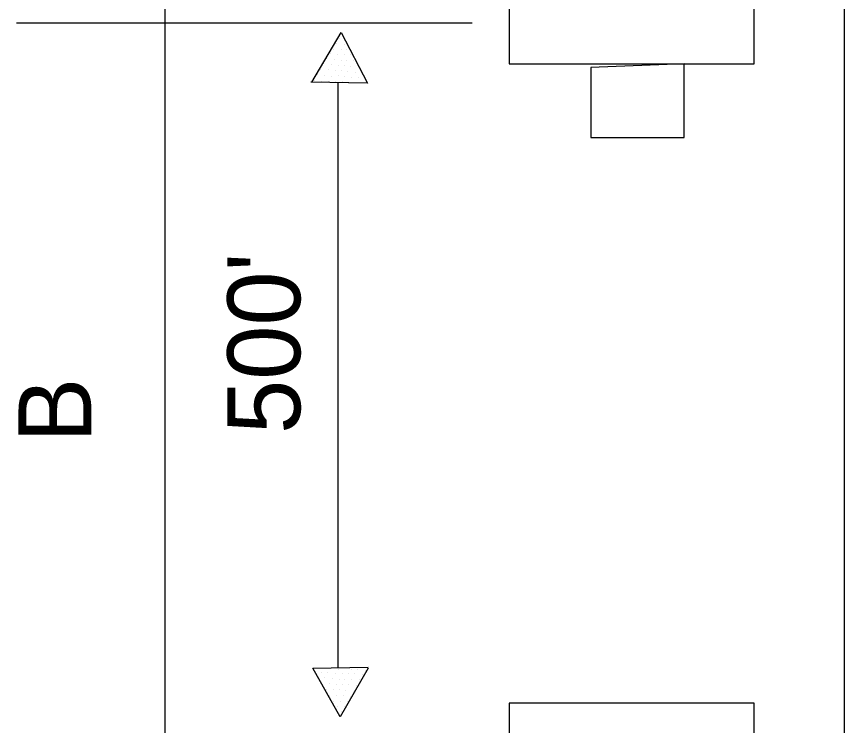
# Model space of a CAD drawing. Extents: x 610.92 to 617.75, y 610.91 to 620.34.
# Drawn here: x 615.127 to 615.809, y 618.599 to 619.182 of the extents above; entities that cross this region are included whole.
import ezdxf

# ---------------------------------------------------------------- set-up
doc = ezdxf.new("R2010")
doc.units = 0
for name, color, linetype in [('DETL-DIMS', 7, 'Continuous'), ('DETL-LINE', 7, 'Continuous'), ('DETL-NOTE', 7, 'Continuous'), ('USER-BORD', 7, 'Continuous')]:
    doc.layers.add(name, color=color, linetype=linetype)

# ---------------------------------------------------------------- blocks, each defined once
blk = doc.blocks.new('SIGN15')
at = {"layer": 'USER-BORD'}
for points in [[(-0.0013, 0.0018), (0.0011, 0.0019), (0.0011, 0.0037), (-0.0013, 0.0037)], [(-0.0031, 0.0018), (-0.0031, 0), (0.0032, 0), (0.0032, 0.0018)]]:
    blk.add_lwpolyline(points, close=True, dxfattribs=at)

msp = doc.modelspace()

# ---------------------------------------------------------------- linework, layer by layer
at = {"layer": 'DETL-DIMS'}
for p, q in [((615.24936, 618.082), (615.24936, 619.7948)), ((615.12696, 619.1772), (615.50216, 619.1772)), ((615.37016, 619.1284), (615.39416, 619.1692)), ((615.37016, 619.1284), (615.39416, 619.1692)), ((615.37016, 619.1284), (615.39416, 619.1692)), ((615.37016, 619.1284), (615.39416, 619.1692)), ((615.39416, 619.1692), (615.41576, 619.1276)), ((615.39416, 619.1692), (615.41576, 619.1276)), ((615.39416, 619.1692), (615.41576, 619.1276)), ((615.39416, 619.1692), (615.41576, 619.1276)), ((615.39016, 619.1604), (615.39016, 619.1604)), ((615.39016, 619.1604), (615.39016, 619.1604)), ((615.39016, 619.1604), (615.39016, 619.1604)), ((615.39016, 619.1604), (615.39016, 619.1604)), ((615.39256, 619.1644), (615.39256, 619.1644)), ((615.39256, 619.1644), (615.39256, 619.1644)), ((615.39256, 619.1644), (615.39256, 619.1644)), ((615.39256, 619.1644), (615.39256, 619.1644)), ((615.39656, 619.1596), (615.39656, 619.1596)), ((615.39656, 619.1596), (615.39656, 619.1596)), ((615.39656, 619.1596), (615.39656, 619.1596)), ((615.39656, 619.1596), (615.39656, 619.1596)), ((615.38776, 619.1556), (615.38776, 619.1556)), ((615.38776, 619.1556), (615.38776, 619.1556)), ((615.38776, 619.1556), (615.38776, 619.1556)), ((615.38776, 619.1556), (615.38776, 619.1556)), ((615.39416, 619.1556), (615.39416, 619.1556)), ((615.39416, 619.1556), (615.39416, 619.1556)), ((615.39416, 619.1556), (615.39416, 619.1556)), ((615.39416, 619.1556), (615.39416, 619.1556)), ((615.39896, 619.1556), (615.39896, 619.1556)), ((615.39896, 619.1556), (615.39896, 619.1556)), ((615.39896, 619.1556), (615.39896, 619.1556)), ((615.39896, 619.1556), (615.39896, 619.1556)), ((615.38216, 619.1476), (615.38216, 619.1476)), ((615.38216, 619.1476), (615.38216, 619.1476)), ((615.38216, 619.1476), (615.38216, 619.1476)), ((615.38216, 619.1476), (615.38216, 619.1476)), ((615.38536, 619.1516), (615.38536, 619.1516)), ((615.38536, 619.1516), (615.38536, 619.1516)), ((615.38536, 619.1516), (615.38536, 619.1516)), ((615.38536, 619.1516), (615.38536, 619.1516)), ((615.38856, 619.1468), (615.38856, 619.1468)), ((615.38856, 619.1468), (615.38856, 619.1468)), ((615.38856, 619.1468), (615.38856, 619.1468)), ((615.38856, 619.1468), (615.38856, 619.1468)), ((615.39096, 619.1508), (615.39096, 619.1508)), ((615.39096, 619.1508), (615.39096, 619.1508)), ((615.39096, 619.1508), (615.39096, 619.1508)), ((615.39096, 619.1508), (615.39096, 619.1508)), ((615.39416, 619.146), (615.39416, 619.146)), ((615.39416, 619.146), (615.39416, 619.146)), ((615.39416, 619.146), (615.39416, 619.146)), ((615.39416, 619.146), (615.39416, 619.146)), ((615.39656, 619.1508), (615.39656, 619.1508)), ((615.39656, 619.1508), (615.39656, 619.1508)), ((615.39656, 619.1508), (615.39656, 619.1508)), ((615.39656, 619.1508), (615.39656, 619.1508)), ((615.39896, 619.146), (615.39896, 619.146)), ((615.39896, 619.146), (615.39896, 619.146)), ((615.39896, 619.146), (615.39896, 619.146)), ((615.39896, 619.146), (615.39896, 619.146)), ((615.40216, 619.1508), (615.40216, 619.1508)), ((615.40216, 619.1508), (615.40216, 619.1508)), ((615.40216, 619.1508), (615.40216, 619.1508)), ((615.40216, 619.1508), (615.40216, 619.1508)), ((615.40456, 619.146), (615.40456, 619.146)), ((615.40456, 619.146), (615.40456, 619.146)), ((615.40456, 619.146), (615.40456, 619.146)), ((615.40456, 619.146), (615.40456, 619.146)), ((615.37736, 619.1388), (615.37736, 619.1388)), ((615.37736, 619.1388), (615.37736, 619.1388)), ((615.37736, 619.1388), (615.37736, 619.1388)), ((615.37736, 619.1388), (615.37736, 619.1388)), ((615.37976, 619.1436), (615.37976, 619.1436)), ((615.37976, 619.1436), (615.37976, 619.1436)), ((615.37976, 619.1436), (615.37976, 619.1436)), ((615.37976, 619.1436), (615.37976, 619.1436)), ((615.38376, 619.1388), (615.38376, 619.1388)), ((615.38376, 619.1388), (615.38376, 619.1388)), ((615.38376, 619.1388), (615.38376, 619.1388)), ((615.38376, 619.1388), (615.38376, 619.1388)), ((615.38616, 619.1428), (615.38616, 619.1428)), ((615.38616, 619.1428), (615.38616, 619.1428)), ((615.38616, 619.1428), (615.38616, 619.1428)), ((615.38616, 619.1428), (615.38616, 619.1428)), ((615.39176, 619.142), (615.39176, 619.142)), ((615.39176, 619.142), (615.39176, 619.142)), ((615.39176, 619.142), (615.39176, 619.142)), ((615.39176, 619.142), (615.39176, 619.142)), ((615.39656, 619.142), (615.39656, 619.142)), ((615.39656, 619.142), (615.39656, 619.142)), ((615.39656, 619.142), (615.39656, 619.142)), ((615.39656, 619.142), (615.39656, 619.142)), ((615.40216, 619.1412), (615.40216, 619.1412)), ((615.40216, 619.1412), (615.40216, 619.1412)), ((615.40216, 619.1412), (615.40216, 619.1412)), ((615.40216, 619.1412), (615.40216, 619.1412)), ((615.40856, 619.1404), (615.40856, 619.1404)), ((615.40856, 619.1404), (615.40856, 619.1404)), ((615.40856, 619.1404), (615.40856, 619.1404)), ((615.40856, 619.1404), (615.40856, 619.1404)), ((615.37496, 619.1348), (615.37496, 619.1348)), ((615.37496, 619.1348), (615.37496, 619.1348)), ((615.37496, 619.1348), (615.37496, 619.1348)), ((615.37496, 619.1348), (615.37496, 619.1348)), ((615.38056, 619.134), (615.38056, 619.134)), ((615.38056, 619.134), (615.38056, 619.134)), ((615.38056, 619.134), (615.38056, 619.134)), ((615.38056, 619.134), (615.38056, 619.134)), ((615.38616, 619.1332), (615.38616, 619.1332)), ((615.38616, 619.1332), (615.38616, 619.1332)), ((615.38616, 619.1332), (615.38616, 619.1332)), ((615.38616, 619.1332), (615.38616, 619.1332)), ((615.38936, 619.138), (615.38936, 619.138)), ((615.38936, 619.138), (615.38936, 619.138)), ((615.38936, 619.138), (615.38936, 619.138)), ((615.38936, 619.138), (615.38936, 619.138)), ((615.39176, 619.134), (615.39176, 619.134)), ((615.39176, 619.134), (615.39176, 619.134)), ((615.39176, 619.134), (615.39176, 619.134)), ((615.39176, 619.134), (615.39176, 619.134)), ((615.39416, 619.138), (615.39416, 619.138)), ((615.39416, 619.138), (615.39416, 619.138)), ((615.39416, 619.138), (615.39416, 619.138)), ((615.39416, 619.138), (615.39416, 619.138)), ((615.39736, 619.1332), (615.39736, 619.1332)), ((615.39736, 619.1332), (615.39736, 619.1332)), ((615.39736, 619.1332), (615.39736, 619.1332)), ((615.39736, 619.1332), (615.39736, 619.1332)), ((615.39976, 619.1372), (615.39976, 619.1372)), ((615.39976, 619.1372), (615.39976, 619.1372)), ((615.39976, 619.1372), (615.39976, 619.1372)), ((615.39976, 619.1372), (615.39976, 619.1372)), ((615.40296, 619.1324), (615.40296, 619.1324)), ((615.40296, 619.1324), (615.40296, 619.1324)), ((615.40296, 619.1324), (615.40296, 619.1324)), ((615.40296, 619.1324), (615.40296, 619.1324)), ((615.40616, 619.1364), (615.40616, 619.1364)), ((615.40616, 619.1364), (615.40616, 619.1364)), ((615.40616, 619.1364), (615.40616, 619.1364)), ((615.40616, 619.1364), (615.40616, 619.1364)), ((615.40856, 619.1324), (615.40856, 619.1324)), ((615.40856, 619.1324), (615.40856, 619.1324)), ((615.40856, 619.1324), (615.40856, 619.1324)), ((615.40856, 619.1324), (615.40856, 619.1324)), ((615.36936, 619.1284), (615.36936, 619.1284)), ((615.41576, 619.1276), (615.36936, 619.1284)), ((615.41576, 619.1276), (615.36936, 619.1284)), ((615.36936, 619.1284), (615.36936, 619.1284)), ((615.36936, 619.1284), (615.36936, 619.1284)), ((615.41576, 619.1276), (615.36936, 619.1284)), ((615.41576, 619.1276), (615.36936, 619.1284)), ((615.36936, 619.1284), (615.36936, 619.1284)), ((615.37256, 619.13), (615.37256, 619.13)), ((615.37256, 619.13), (615.37256, 619.13)), ((615.37256, 619.13), (615.37256, 619.13)), ((615.37256, 619.13), (615.37256, 619.13)), ((615.37816, 619.1292), (615.37816, 619.1292)), ((615.37816, 619.1292), (615.37816, 619.1292)), ((615.37816, 619.1292), (615.37816, 619.1292)), ((615.37816, 619.1292), (615.37816, 619.1292)), ((615.38376, 619.1292), (615.38376, 619.1292)), ((615.38376, 619.1292), (615.38376, 619.1292)), ((615.38376, 619.1292), (615.38376, 619.1292)), ((615.38376, 619.1292), (615.38376, 619.1292)), ((615.38936, 619.1292), (615.38936, 619.1292)), ((615.38936, 619.1292), (615.38936, 619.1292)), ((615.38936, 619.1292), (615.38936, 619.1292)), ((615.38936, 619.1292), (615.38936, 619.1292)), ((615.39176, 618.6468), (615.39176, 619.1284)), ((615.39496, 619.1292), (615.39496, 619.1292)), ((615.39496, 619.1292), (615.39496, 619.1292)), ((615.39496, 619.1292), (615.39496, 619.1292)), ((615.39496, 619.1292), (615.39496, 619.1292)), ((615.40056, 619.1284), (615.40056, 619.1284)), ((615.40056, 619.1284), (615.40056, 619.1284)), ((615.40056, 619.1284), (615.40056, 619.1284)), ((615.40056, 619.1284), (615.40056, 619.1284)), ((615.39176, 618.6692), (615.39176, 619.0932)), ((615.39176, 618.6692), (615.39176, 619.0932)), ((615.39176, 618.6692), (615.39176, 619.0932)), ((615.37096, 618.646), (615.41656, 618.6468)), ((615.37096, 618.646), (615.41656, 618.6468)), ((615.37096, 618.646), (615.41656, 618.6468)), ((615.37096, 618.646), (615.41656, 618.6468)), ((615.39336, 618.606), (615.37096, 618.646)), ((615.39336, 618.606), (615.37096, 618.646)), ((615.39336, 618.606), (615.37096, 618.646)), ((615.39336, 618.606), (615.37096, 618.646)), ((615.37816, 618.642), (615.37816, 618.642)), ((615.37816, 618.642), (615.37816, 618.642)), ((615.37816, 618.642), (615.37816, 618.642)), ((615.37816, 618.642), (615.37816, 618.642)), ((615.38296, 618.642), (615.38296, 618.642)), ((615.38296, 618.642), (615.38296, 618.642)), ((615.38296, 618.642), (615.38296, 618.642)), ((615.38296, 618.642), (615.38296, 618.642)), ((615.38536, 618.646), (615.38536, 618.646)), ((615.38536, 618.646), (615.38536, 618.646)), ((615.38536, 618.646), (615.38536, 618.646)), ((615.38536, 618.646), (615.38536, 618.646)), ((615.38936, 618.6412), (615.38936, 618.6412)), ((615.38936, 618.6412), (615.38936, 618.6412)), ((615.38936, 618.6412), (615.38936, 618.6412)), ((615.38936, 618.6412), (615.38936, 618.6412)), ((615.39176, 618.6452), (615.39176, 618.6452)), ((615.39176, 618.6452), (615.39176, 618.6452)), ((615.39176, 618.6452), (615.39176, 618.6452)), ((615.39176, 618.6452), (615.39176, 618.6452)), ((615.41656, 618.646), (615.39336, 618.606)), ((615.41656, 618.646), (615.39336, 618.606)), ((615.41656, 618.646), (615.39336, 618.606)), ((615.41656, 618.646), (615.39336, 618.606)), ((615.39496, 618.6412), (615.39496, 618.6412)), ((615.39496, 618.6412), (615.39496, 618.6412)), ((615.39496, 618.6412), (615.39496, 618.6412)), ((615.39496, 618.6412), (615.39496, 618.6412)), ((615.39736, 618.646), (615.39736, 618.646)), ((615.39736, 618.646), (615.39736, 618.646)), ((615.39736, 618.646), (615.39736, 618.646)), ((615.39736, 618.646), (615.39736, 618.646)), ((615.40056, 618.6412), (615.40056, 618.6412)), ((615.40056, 618.6412), (615.40056, 618.6412)), ((615.40056, 618.6412), (615.40056, 618.6412)), ((615.40056, 618.6412), (615.40056, 618.6412)), ((615.40296, 618.6452), (615.40296, 618.6452)), ((615.40296, 618.6452), (615.40296, 618.6452)), ((615.40296, 618.6452), (615.40296, 618.6452)), ((615.40296, 618.6452), (615.40296, 618.6452)), ((615.40536, 618.6412), (615.40536, 618.6412)), ((615.40536, 618.6412), (615.40536, 618.6412)), ((615.40536, 618.6412), (615.40536, 618.6412)), ((615.40536, 618.6412), (615.40536, 618.6412)), ((615.40776, 618.6452), (615.40776, 618.6452)), ((615.40776, 618.6452), (615.40776, 618.6452)), ((615.40776, 618.6452), (615.40776, 618.6452)), ((615.40776, 618.6452), (615.40776, 618.6452)), ((615.41416, 618.6444), (615.41416, 618.6444)), ((615.41416, 618.6444), (615.41416, 618.6444)), ((615.41416, 618.6444), (615.41416, 618.6444)), ((615.41416, 618.6444), (615.41416, 618.6444)), ((615.41656, 618.6468), (615.41656, 618.6468)), ((615.41656, 618.6468), (615.41656, 618.6468)), ((615.41656, 618.6468), (615.41656, 618.6468)), ((615.41656, 618.6468), (615.41656, 618.6468)), ((615.38056, 618.638), (615.38056, 618.638)), ((615.38056, 618.638), (615.38056, 618.638)), ((615.38056, 618.638), (615.38056, 618.638)), ((615.38056, 618.638), (615.38056, 618.638)), ((615.38696, 618.6372), (615.38696, 618.6372)), ((615.38696, 618.6372), (615.38696, 618.6372)), ((615.38696, 618.6372), (615.38696, 618.6372)), ((615.38696, 618.6372), (615.38696, 618.6372)), ((615.39256, 618.6364), (615.39256, 618.6364)), ((615.39256, 618.6364), (615.39256, 618.6364)), ((615.39256, 618.6364), (615.39256, 618.6364)), ((615.39256, 618.6364), (615.39256, 618.6364)), ((615.39736, 618.6364), (615.39736, 618.6364)), ((615.39736, 618.6364), (615.39736, 618.6364)), ((615.39736, 618.6364), (615.39736, 618.6364)), ((615.39736, 618.6364), (615.39736, 618.6364)), ((615.40296, 618.6364), (615.40296, 618.6364)), ((615.40296, 618.6364), (615.40296, 618.6364)), ((615.40296, 618.6364), (615.40296, 618.6364)), ((615.40296, 618.6364), (615.40296, 618.6364)), ((615.40936, 618.6364), (615.40936, 618.6364)), ((615.40936, 618.6364), (615.40936, 618.6364)), ((615.40936, 618.6364), (615.40936, 618.6364)), ((615.40936, 618.6364), (615.40936, 618.6364)), ((615.41176, 618.6404), (615.41176, 618.6404)), ((615.41176, 618.6404), (615.41176, 618.6404)), ((615.41176, 618.6404), (615.41176, 618.6404)), ((615.41176, 618.6404), (615.41176, 618.6404)), ((615.37816, 618.6332), (615.37816, 618.6332)), ((615.37816, 618.6332), (615.37816, 618.6332)), ((615.37816, 618.6332), (615.37816, 618.6332)), ((615.37816, 618.6332), (615.37816, 618.6332)), ((615.38216, 618.6284), (615.38216, 618.6284)), ((615.38216, 618.6284), (615.38216, 618.6284)), ((615.38216, 618.6284), (615.38216, 618.6284)), ((615.38216, 618.6284), (615.38216, 618.6284)), ((615.38456, 618.6332), (615.38456, 618.6332)), ((615.38456, 618.6332), (615.38456, 618.6332)), ((615.38456, 618.6332), (615.38456, 618.6332)), ((615.38456, 618.6332), (615.38456, 618.6332)), ((615.38776, 618.6284), (615.38776, 618.6284)), ((615.38776, 618.6284), (615.38776, 618.6284)), ((615.38776, 618.6284), (615.38776, 618.6284)), ((615.38776, 618.6284), (615.38776, 618.6284)), ((615.39016, 618.6324), (615.39016, 618.6324)), ((615.39016, 618.6324), (615.39016, 618.6324)), ((615.39016, 618.6324), (615.39016, 618.6324)), ((615.39016, 618.6324), (615.39016, 618.6324)), ((615.39256, 618.6284), (615.39256, 618.6284)), ((615.39256, 618.6284), (615.39256, 618.6284)), ((615.39256, 618.6284), (615.39256, 618.6284)), ((615.39256, 618.6284), (615.39256, 618.6284)), ((615.39496, 618.6324), (615.39496, 618.6324)), ((615.39496, 618.6324), (615.39496, 618.6324)), ((615.39496, 618.6324), (615.39496, 618.6324)), ((615.39496, 618.6324), (615.39496, 618.6324)), ((615.39816, 618.6276), (615.39816, 618.6276)), ((615.39816, 618.6276), (615.39816, 618.6276)), ((615.39816, 618.6276), (615.39816, 618.6276)), ((615.39816, 618.6276), (615.39816, 618.6276)), ((615.40056, 618.6324), (615.40056, 618.6324)), ((615.40056, 618.6324), (615.40056, 618.6324)), ((615.40056, 618.6324), (615.40056, 618.6324)), ((615.40056, 618.6324), (615.40056, 618.6324)), ((615.40696, 618.6316), (615.40696, 618.6316)), ((615.40696, 618.6316), (615.40696, 618.6316)), ((615.40696, 618.6316), (615.40696, 618.6316)), ((615.40696, 618.6316), (615.40696, 618.6316)), ((615.38456, 618.6236), (615.38456, 618.6236)), ((615.38456, 618.6236), (615.38456, 618.6236)), ((615.38456, 618.6236), (615.38456, 618.6236)), ((615.38456, 618.6236), (615.38456, 618.6236)), ((615.39016, 618.6236), (615.39016, 618.6236)), ((615.39016, 618.6236), (615.39016, 618.6236)), ((615.39016, 618.6236), (615.39016, 618.6236)), ((615.39016, 618.6236), (615.39016, 618.6236)), ((615.39576, 618.6236), (615.39576, 618.6236)), ((615.39576, 618.6236), (615.39576, 618.6236)), ((615.39576, 618.6236), (615.39576, 618.6236)), ((615.39576, 618.6236), (615.39576, 618.6236)), ((615.40216, 618.6228), (615.40216, 618.6228)), ((615.40216, 618.6228), (615.40216, 618.6228)), ((615.40216, 618.6228), (615.40216, 618.6228)), ((615.40216, 618.6228), (615.40216, 618.6228)), ((615.40456, 618.6268), (615.40456, 618.6268)), ((615.40456, 618.6268), (615.40456, 618.6268)), ((615.40456, 618.6268), (615.40456, 618.6268)), ((615.40456, 618.6268), (615.40456, 618.6268)), ((615.38776, 618.6188), (615.38776, 618.6188)), ((615.38776, 618.6188), (615.38776, 618.6188)), ((615.38776, 618.6188), (615.38776, 618.6188)), ((615.38776, 618.6188), (615.38776, 618.6188)), ((615.39096, 618.6148), (615.39096, 618.6148)), ((615.39096, 618.6148), (615.39096, 618.6148)), ((615.39096, 618.6148), (615.39096, 618.6148)), ((615.39096, 618.6148), (615.39096, 618.6148)), ((615.39336, 618.6188), (615.39336, 618.6188)), ((615.39336, 618.6188), (615.39336, 618.6188)), ((615.39336, 618.6188), (615.39336, 618.6188)), ((615.39336, 618.6188), (615.39336, 618.6188)), ((615.39656, 618.614), (615.39656, 618.614)), ((615.39656, 618.614), (615.39656, 618.614)), ((615.39656, 618.614), (615.39656, 618.614)), ((615.39656, 618.614), (615.39656, 618.614)), ((615.39976, 618.6188), (615.39976, 618.6188)), ((615.39976, 618.6188), (615.39976, 618.6188)), ((615.39976, 618.6188), (615.39976, 618.6188)), ((615.39976, 618.6188), (615.39976, 618.6188)), ((615.39416, 618.61), (615.39416, 618.61)), ((615.39416, 618.61), (615.39416, 618.61)), ((615.39416, 618.61), (615.39416, 618.61)), ((615.39416, 618.61), (615.39416, 618.61))]:
    msp.add_line(p, q, dxfattribs=at)
at = {"layer": 'DETL-LINE'}
msp.add_line((615.80856, 613.3204), (615.80856, 620.3372), dxfattribs=at)

# ---------------------------------------------------------------- block references
at = {"layer": 'DETL-LINE', "xscale": 32, "yscale": 32, "rotation": 180}
for p in [(615.63492, 619.20116), (615.63492, 618.61716)]:
    msp.add_blockref('SIGN15', p, dxfattribs=at)

# ---------------------------------------------------------------- texts
at = {"layer": 'DETL-NOTE'}
for s, p in [("500'", (615.36052, 618.83876)), ('B', (615.18852, 618.83156))]:
    msp.add_text(s, height=0.06, rotation=90, dxfattribs=at).set_placement(p)

doc.saveas('drawing.dxf')
